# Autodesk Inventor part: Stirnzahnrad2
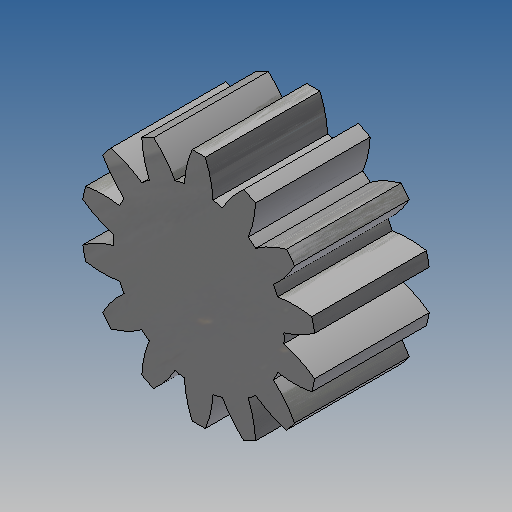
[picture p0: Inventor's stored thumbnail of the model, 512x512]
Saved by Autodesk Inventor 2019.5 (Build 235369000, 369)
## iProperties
Created: 2021-12
Part Number: Stirnzahnrad2
Material: Steel
Document SubType Name: Modeling
Categories: <?xml version="1.0" encoding="UTF-16"?> <MemberInstance><Categories><FamilyTemplate><FamilyTemplateParameter ValueType="xs:double" Id="1" ObjectReferenceKey="da
Mass: 1.27364 g
Surface Area: 2.59778 cm^2
Volume: 0.162248 cm^3
Density: 7.85 g/cm^3
Appearance: Steel
CustomPartVersion: 1
Mass: 0
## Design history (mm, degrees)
sketch "Sketch1"
  geometry: C1 r 4.105 at (0, 0)
  constraints: 1 centre point
  dimensions: "d0" = 8.21 diameter of C1 (= da_da)
extrude "Extrusion1" new body sketch "Sketch1" distance "d1" = 4 (= da_b); taper "d2" = 0 deg
workplane "Work Plane2"
sketch "Sketch2"
  geometry: C1 r 4.105 at (0, 0) reference; C2 r 3.5 at (0, 0)
  constraints: 1 centre point, 1 coincident
  dimensions: "d3" = 7 diameter of C2 (= da_dw)
feature "Flankendurchmesser" sketch "Sketch2" dims "d4" = 10, "d5" = 0
workplane "Work Plane8"
workplane "Work Plane9"
feature "Stirnzahnrad" dims "da_b" = 4, "da_d" = 7, "da_aw" = 35.5, "da_da" = 8.21, "da_df" = 5.96, "da_dw" = 7, angle "da_beta" = 0 deg, "da_lefttooth" = 0, "da_righttooth" = 0
body "Solid1"
body "Srf1"
other parameters: "d16" = 35.5 (= da_aw), "d17" = 0, "d34" = 2.24399 (computed from da_z), "d39" = 0, "d41" = 0, "d43" = 35.5 (= da_aw), "d46" = 35.5 (= da_aw), "d47" = 0, "d48" = 0
